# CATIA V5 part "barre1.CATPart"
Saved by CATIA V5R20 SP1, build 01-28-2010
Part number: barre1
Publications: "Plan.1", "A", "C", "axe_1_0", "axe_1_4", "Droite.1"
Bounding box of the stored display mesh (mm): x -10 to 10, y -199.605 to 0, z 0 to 12.558
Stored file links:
  C:\Users\patrice\Desktop\IFMa\Semestre 3\IAO\projet iao\iao\barre1.CATPart
  C:\Users\patrice\Desktop\IFMa\Semestre 3\IAO\projet iao\iao\skl_iao_755.CATProduct
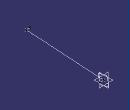
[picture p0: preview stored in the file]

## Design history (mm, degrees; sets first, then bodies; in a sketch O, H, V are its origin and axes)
Set1
  Plane1: linked copy from another document
  Point1 "A": linked copy from another document
  Point2 "C": linked copy from another document
Set2
  Plane2: type Offset, RefPlane Plane1, Offset 0
  Point3 "A": (0, 0, 0), relative to Point1
  Point4 "C": (0, 0, 0), relative to Point2
  Line1: type PtPt, FirstPoint Point3, SecondPoint Point4
  Line2 "axe_1_0": type Normal, RefPoint Point3, RefSkin Plane2, Start 0, End 10
  Line3 "axe_1_4": type Normal, RefPoint Point4, RefSkin Plane2, Start 0, End 10
Body1 (main body)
